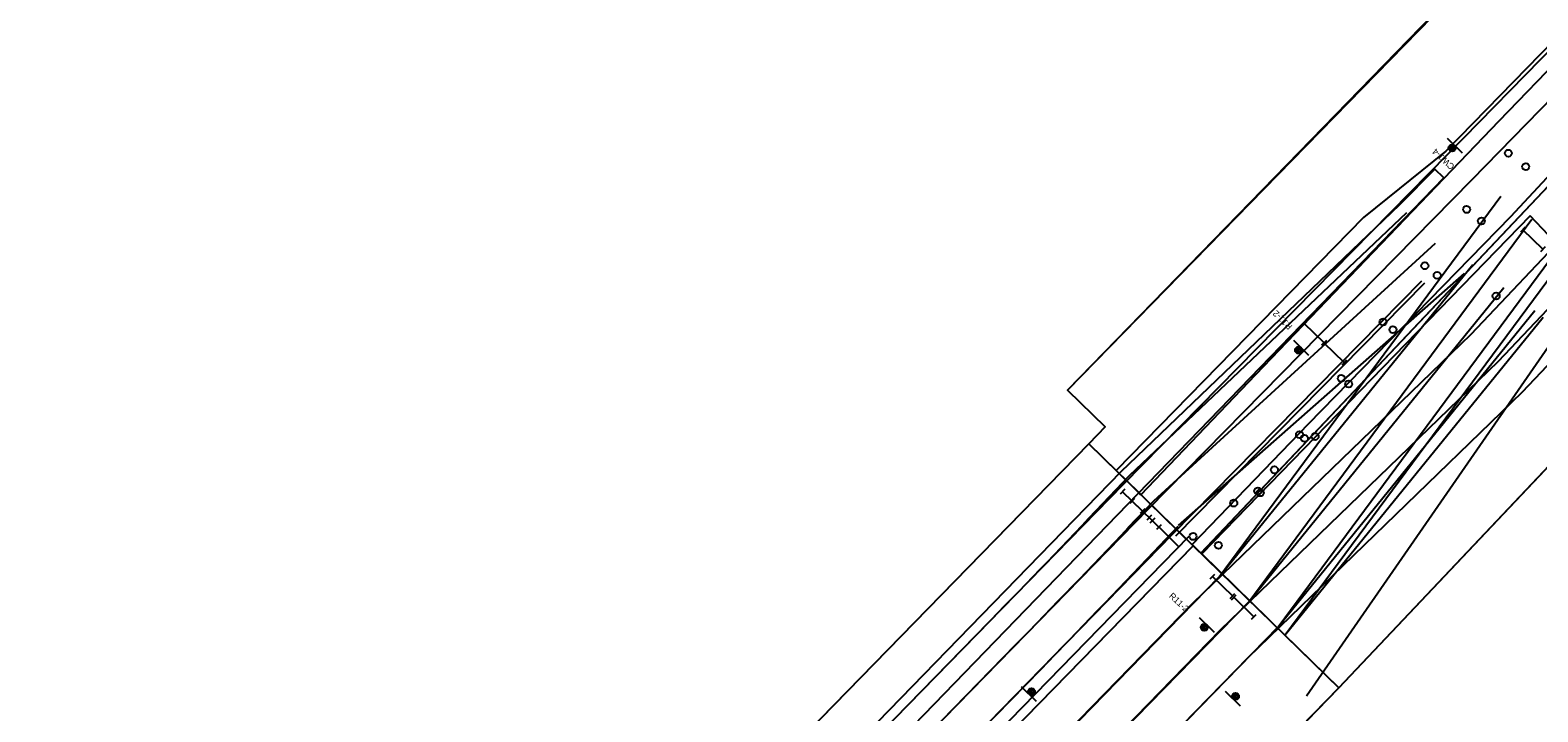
# Model space of a CAD drawing. Extents: x 2252379 to 2256472, y 13788212 to 13792539.
# Drawn here: x 2255390.1 to 2255820.2, y 13791557.4 to 13791752 of the extents above; entities that cross this region are included whole.
import ezdxf

# ---------------------------------------------------------------- set-up
doc = ezdxf.new("R2010")
doc.units = 0
for name, color, linetype in [('D_TCP_OVERALL_PATT', 7, 'Continuous'), ('D_TCP_PH_1_BARREL', 7, 'Continuous'), ('D_TCP_PH_1_BARRIER', 7, 'Continuous'), ('D_TCP_PH_1_MISC', 7, 'Continuous'), ('D_TCP_PH_1_PATT', 7, 'Continuous'), ('D_TCP_PH_1_SIGN', 7, 'Continuous'), ('D_TCP_PH_1_TEMP_PVMNT', 7, 'Continuous'), ('D_TCP_PH_1_WZPM_NRMV_4IN_W_SLD', 7, 'Continuous'), ('D_TCP_PH_1_WZPM_RMV_4IN_Y_SLD', 7, 'Continuous'), ('D_TCP_PH_1A_BARREL', 7, 'Continuous'), ('D_TCP_PH_1A_BARRIER', 7, 'Continuous'), ('D_TCP_PH_1A_PATT', 7, 'Continuous'), ('D_TCP_PH_1A_SIGN', 7, 'Continuous'), ('D_TCP_PH_1A_TEMP_DRN', 7, 'Continuous'), ('D_TCP_PH_1A_TEMP_PVMNT', 7, 'Continuous'), ('D_TCP_PH_1A_WZPM_NRMV_4IN_W_SLD', 7, 'Continuous'), ('D_TCP_PH_1A_WZPM_RMV_4IN_Y_SLD', 7, 'Continuous'), ('D_TCP_PH_1B_BARREL', 7, 'Continuous'), ('D_TCP_PH_1B_BARRIER', 7, 'Continuous'), ('D_TCP_PH_1B_TEMP_PVMNT', 7, 'Continuous'), ('D_TCP_PH_1B_WZPM_NRMV_4IN_W_SLD', 7, 'Continuous'), ('D_TCP_PH_1B_WZPM_RMV_4IN_Y_SLD', 7, 'Continuous'), ('D_TCP_PH_2_BARRIER', 7, 'Continuous'), ('D_TCP_PH_2_MISC', 7, 'Continuous'), ('D_TCP_PH_2_PATT', 7, 'Continuous'), ('D_TCP_PH_2_TEMP_PVMNT', 7, 'Continuous'), ('D_TCP_PH_2_WZPM_NRMV_4IN_W_SLD', 7, 'Continuous'), ('D_TCP_PH_2_WZPM_NRMV_4IN_Y_SLD', 7, 'Continuous'), ('D_TCP_PH_2A_BARREL', 7, 'Continuous'), ('D_TCP_PH_2A_PATT', 7, 'Continuous'), ('D_TCP_PH_2A_WZPM_NRMV_4IN_W_SLD', 7, 'Continuous'), ('D_TCP_PH_2A_WZPM_RMV_4IN_Y_SLD', 7, 'Continuous'), ('E_Structure_Sign_Sign And Post Single_SGN', 7, 'Continuous'), ('Level 1', 7, 'Continuous'), ('SIGN_DESCR', 7, 'Continuous')]:
    doc.layers.add(name, color=color, linetype=linetype)

# ---------------------------------------------------------------- blocks, each defined once
blk = doc.blocks.new('TYP3')
at = {"layer": 'Level 1'}
for p, q in [((-0.165, 0.04), (-0.165, -0.04)), ((0.163, 0), (-0.163, 0)), ((0.163, 0.04), (0.163, -0.04))]:
    blk.add_line(p, q, dxfattribs=at)
blk = doc.blocks.new('SGN')
at = {"layer": 'E_Structure_Sign_Sign And Post Single_SGN'}
blk.add_line((0.6, -0.2), (-0.6, -0.2), dxfattribs=at)
for radius in [0.2, 0.137, 0.0611]:
    blk.add_circle((0, 0), radius, dxfattribs=at)

msp = doc.modelspace()

# ---------------------------------------------------------------- linework, layer by layer
at = {"layer": 'D_TCP_OVERALL_PATT'}
for p, q in [((2255859.06, 13791745.48), (2255724.02, 13791602.73)), ((2255724.02, 13791602.73), (2255858.62, 13791745.02)), ((2255685.97, 13791649.23), (2255696.75, 13791638.72)), ((2255696.75, 13791638.72), (2255692.07, 13791633.92)), ((2255692.07, 13791633.92), (2255472.33, 13791408.61)), ((2255720.66, 13791606.02), (2255692.07, 13791633.92)), ((2255692.07, 13791633.92), (2255724.02, 13791602.73)), ((2255720.66, 13791606.02), (2255692.07, 13791633.92)), ((2255721.86, 13791604.85), (2255480.34, 13791357.3)), ((2255483.41, 13791360.45), (2255721.86, 13791604.85)), ((2255503.41, 13791380.95), (2255721.86, 13791604.85)), ((2255760.02, 13791567.61), (2255720.66, 13791606.02)), ((2255721.86, 13791604.85), (2255720.66, 13791606.02)), ((2255763.39, 13791564.32), (2255721.86, 13791604.85))]:
    msp.add_line(p, q, dxfattribs=at)
for points in [[(2256262.44, 13792241.68), (2255950.04, 13791921.35), (2255949.84, 13791921.15), (2255818.04, 13791784.57), (2255685.97, 13791649.23)], [(2255763.39, 13791564.32), (2255898.58, 13791707.23), (2255898.79, 13791707.44)], [(2255692.07, 13791633.92), (2255473.67, 13791409.98), (2255472.33, 13791408.61)], [(2255724.02, 13791602.73), (2255724.02, 13791602.73), (2255760.02, 13791567.61), (2255763.39, 13791564.32)], [(2255104.28, 13790888.18), (2255118.36, 13790881.14), (2255128.85, 13790888.25), (2255137.45, 13790895.94), (2255142.38, 13790905.75), (2255131.78, 13790916.36), (2255285.15, 13791073.53), (2255300.44, 13791089.2), (2255318.42, 13791107.62), (2255362.49, 13791152.79), (2255763.39, 13791564.32)]]:
    msp.add_lwpolyline(points, dxfattribs=at)
at = {"layer": 'D_TCP_PH_1_BARREL'}
for centre in [(2255756.65, 13791636), (2255745.04, 13791626.49), (2255733.44, 13791616.99), (2255721.83, 13791607.48)]:
    msp.add_circle(centre, 1, dxfattribs=at)
at = {"layer": 'D_TCP_PH_1_BARRIER'}
msp.add_line((2255497.24, 13791378.38), (2255720.62, 13791607.51), dxfattribs=at)
at = {"layer": 'D_TCP_PH_1_PATT'}
for p, q in [((2255721.86, 13791604.85), (2255480.34, 13791357.3)), ((2255763.39, 13791564.32), (2255721.86, 13791604.85))]:
    msp.add_line(p, q, dxfattribs=at)
msp.add_lwpolyline([(2255091.3, 13790894.58), (2255104.25, 13790888.15), (2255118.36, 13790881.14), (2255128.85, 13790888.25), (2255137.45, 13790895.94), (2255142.38, 13790905.75), (2255131.78, 13790916.36), (2255295.32, 13791083.95), (2255307.58, 13791096.52), (2255322.25, 13791111.55), (2255663.82, 13791461.58), (2255763.39, 13791564.32)], dxfattribs=at)
at = {"layer": 'D_TCP_PH_1_TEMP_PVMNT'}
for p, q in [((2255488.15, 13791394.52), (2255793.37, 13791709.82)), ((2255701.25, 13791625.9), (2255484.24, 13791402.88))]:
    msp.add_line(p, q, dxfattribs=at)
msp.add_lwpolyline([(2255793.37, 13791709.82), (2255790.81, 13791712.31), (2255780.7, 13791702.08), (2255701.25, 13791625.9)], dxfattribs=at)
at = {"layer": 'D_TCP_PH_1_WZPM_NRMV_4IN_W_SLD'}
for p, q in [((2255703.66, 13791624.86), (2255782.76, 13791699.91)), ((2255717.66, 13791610.56), (2255799.28, 13791682.49)), ((2255696.1, 13791616.87), (2255703.66, 13791624.86)), ((2255710.63, 13791603.12), (2255717.56, 13791610.45)), ((2255485.25, 13791400.28), (2255664.15, 13791583.61)), ((2255488.75, 13791375.24), (2255678.46, 13791569.64))]:
    msp.add_line(p, q, dxfattribs=at)
for radius in [2970, 2990]:
    msp.add_arc((2253538.53, 13793657.89), radius, 315.70035, 316.59007, dxfattribs=at)
at = {"layer": 'D_TCP_PH_1_WZPM_RMV_4IN_Y_SLD'}
for p, q in [((2255710.61, 13791617.66), (2255791.02, 13791691.2)), ((2255703.36, 13791610), (2255710.61, 13791617.66)), ((2255484.04, 13791384.73), (2255671.3, 13791576.63))]:
    msp.add_line(p, q, dxfattribs=at)
msp.add_arc((2253538.53, 13793657.89), 2980, 315.70035, 316.59007, dxfattribs=at)
at = {"layer": 'D_TCP_PH_1A_BARREL'}
for centre in [(2255816.71, 13791713.02), (2255804.08, 13791697.51), (2255791.46, 13791681.99), (2255778.84, 13791666.48), (2255766.22, 13791650.96), (2255753.6, 13791635.45), (2255740.98, 13791619.93), (2255729.05, 13791604.92)]:
    msp.add_circle(centre, 1, dxfattribs=at)
at = {"layer": 'D_TCP_PH_1A_BARRIER'}
for p, q in [((2255754.13, 13791669.01), (2255752.79, 13791667.63)), ((2255759.19, 13791662.73), (2255753.5, 13791668.28)), ((2255759.86, 13791663.42), (2255758.51, 13791662.04))]:
    msp.add_line(p, q, dxfattribs=at)
at = {"layer": 'D_TCP_PH_1A_PATT'}
for p, q in [((2255692.07, 13791633.92), (2255473.67, 13791409.98)), ((2255721.86, 13791604.85), (2255692.07, 13791633.92)), ((2255503.41, 13791380.95), (2255721.86, 13791604.85))]:
    msp.add_line(p, q, dxfattribs=at)
at = {"layer": 'D_TCP_PH_1A_TEMP_DRN'}
msp.add_line((2255828.27, 13791668.94), (2255754.22, 13791561.89), dxfattribs=at)
at = {"layer": 'D_TCP_PH_1A_TEMP_PVMNT'}
for p, q in [((2255748.05, 13791579.29), (2255821.67, 13791670.08)), ((2255721.54, 13791605.16), (2255748.05, 13791579.29)), ((2255721.54, 13791605.16), (2255748.05, 13791579.29))]:
    msp.add_line(p, q, dxfattribs=at)
for points in [[(2255837.05, 13791724.46), (2255824, 13791711.16), (2255812.42, 13791698.73)], [(2255837.05, 13791724.46), (2255824, 13791711.16), (2255812.42, 13791698.73)], [(2255812.42, 13791698.73), (2255754.67, 13791639.55), (2255721.54, 13791605.16)], [(2255812.42, 13791698.73), (2255754.67, 13791639.55), (2255721.54, 13791605.16)]]:
    msp.add_lwpolyline(points, dxfattribs=at)
at = {"layer": 'D_TCP_PH_1A_WZPM_NRMV_4IN_W_SLD'}
for p, q in [((2255729.3, 13791595.99), (2255801.64, 13791685.07)), ((2255746.09, 13791581.7), (2255819.34, 13791671.97)), ((2255511.26, 13791372.53), (2255729.3, 13791595.99)), ((2255516.79, 13791346.7), (2255746.09, 13791581.7))]:
    msp.add_line(p, q, dxfattribs=at)
at = {"layer": 'D_TCP_PH_1A_WZPM_RMV_4IN_Y_SLD'}
for p, q in [((2255737.7, 13791588.84), (2255810.49, 13791678.52)), ((2255508.92, 13791354.38), (2255737.7, 13791588.84))]:
    msp.add_line(p, q, dxfattribs=at)
at = {"layer": 'D_TCP_PH_1B_BARREL'}
for centre in [(2255811.76, 13791716.85), (2255799.85, 13791700.79), (2255787.94, 13791684.72), (2255776.02, 13791668.65), (2255764.11, 13791652.59), (2255752.2, 13791636.52), (2255740.29, 13791620.45), (2255729.05, 13791604.92)]:
    msp.add_circle(centre, 1, dxfattribs=at)
at = {"layer": 'D_TCP_PH_1B_TEMP_PVMNT'}
for p, q in [((2255817.95, 13791698.97), (2255724.29, 13791602.48)), ((2255828.49, 13791687.98), (2255817.95, 13791698.97)), ((2255748.05, 13791579.29), (2255828.49, 13791687.98)), ((2255724.29, 13791602.48), (2255748.05, 13791579.29))]:
    msp.add_line(p, q, dxfattribs=at)
at = {"layer": 'D_TCP_PH_1B_WZPM_NRMV_4IN_W_SLD'}
for p, q in [((2255729.3, 13791595.99), (2255809.65, 13791704.54)), ((2255746.09, 13791581.7), (2255827.33, 13791691.45)), ((2255501.04, 13791362.06), (2255729.3, 13791595.99)), ((2255516.79, 13791346.7), (2255746.09, 13791581.7))]:
    msp.add_line(p, q, dxfattribs=at)
at = {"layer": 'D_TCP_PH_1B_WZPM_RMV_4IN_Y_SLD'}
for p, q in [((2255737.7, 13791588.84), (2255818.49, 13791697.99)), ((2255508.92, 13791354.38), (2255737.7, 13791588.84))]:
    msp.add_line(p, q, dxfattribs=at)
at = {"layer": 'D_TCP_PH_2_BARRIER'}
msp.add_lwpolyline([(2255787.8, 13791679.72), (2255716.82, 13791607.52)], dxfattribs=at)
at = {"layer": 'D_TCP_PH_2_PATT'}
for points in [[(2255724.02, 13791602.73), (2255763.39, 13791564.32), (2255860.93, 13791667.42), (2255898.79, 13791707.44), (2255996.34, 13791810.56), (2256028.89, 13791844.66), (2256225.09, 13792045.83), (2256221.59, 13792049.77), (2256329.19, 13792160.1), (2256336.4, 13792159.97), (2256381.46, 13792159.13), (2256415.88, 13792189.35), (2256355.41, 13792258.24)], [(2255963.47, 13791855.85), (2255947.31, 13791838.77), (2255878.59, 13791766.12), (2255809.87, 13791693.48), (2255741.14, 13791620.83), (2255724.02, 13791602.73)]]:
    msp.add_lwpolyline(points, dxfattribs=at)
at = {"layer": 'D_TCP_PH_2_TEMP_PVMNT'}
for p, q in [((2255824.74, 13791748.96), (2255793.95, 13791717.4)), ((2255793.95, 13791717.4), (2255770.4, 13791698.52)), ((2255770.4, 13791698.52), (2255699.9, 13791626.27)), ((2255699.9, 13791626.27), (2255706.25, 13791620.07)), ((2255706.25, 13791620.07), (2255706.94, 13791619.4))]:
    msp.add_line(p, q, dxfattribs=at)
msp.add_lwpolyline([(2255706.94, 13791619.4), (2255739.78, 13791653.65), (2255809.14, 13791726.04), (2255828.07, 13791745.71)], dxfattribs=at)
at = {"layer": 'D_TCP_PH_2_WZPM_NRMV_4IN_W_SLD'}
for p, q in [((2255702, 13791622.4), (2255794.62, 13791716.66)), ((2255615.61, 13791533.87), (2255702, 13791622.4))]:
    msp.add_line(p, q, dxfattribs=at)
for points in [[(2255794.62, 13791716.66), (2255825.46, 13791748.26)], [(2255715.99, 13791608.1), (2255787.07, 13791680.43)], [(2255629.93, 13791519.9), (2255715.99, 13791608.1)]]:
    msp.add_lwpolyline(points, dxfattribs=at)
at = {"layer": 'D_TCP_PH_2_WZPM_NRMV_4IN_Y_SLD'}
for p, q in [((2255709.11, 13791615.37), (2255801.35, 13791709.24)), ((2255622.77, 13791526.88), (2255709.11, 13791615.37))]:
    msp.add_line(p, q, dxfattribs=at)
msp.add_lwpolyline([(2255801.35, 13791709.24), (2255832.61, 13791741.28)], dxfattribs=at)
at = {"layer": 'D_TCP_PH_2A_BARREL'}
msp.add_circle((2255808.28, 13791676.1), 1, dxfattribs=at)
at = {"layer": 'D_TCP_PH_2A_PATT'}
msp.add_line((2255724.02, 13791602.73), (2255741.14, 13791620.83), dxfattribs=at)
for points in [[(2256355.41, 13792258.24), (2256294.68, 13792327.44), (2256278.09, 13792313.37), (2256275.37, 13792310.98), (2256266.11, 13792319.83), (2256265.3, 13792302.52), (2256262.44, 13792241.68), (2255685.97, 13791649.23), (2255696.75, 13791638.72), (2255692.07, 13791633.92), (2255724.02, 13791602.73)], [(2255741.14, 13791620.83), (2255809.87, 13791693.48), (2255878.59, 13791766.12)]]:
    msp.add_lwpolyline(points, dxfattribs=at)
at = {"layer": 'D_TCP_PH_2A_WZPM_NRMV_4IN_W_SLD'}
for p, q in [((2255801.14, 13791665.2), (2255970.51, 13791844.64)), ((2255815.84, 13791648.73), (2255986.42, 13791829.45))]:
    msp.add_line(p, q, dxfattribs=at)
for points in [[(2255642.78, 13791507.31), (2255721.85, 13791588.58), (2255801.14, 13791665.2)], [(2255658.53, 13791491.94), (2255737.61, 13791573), (2255815.84, 13791648.73)]]:
    msp.add_lwpolyline(points, dxfattribs=at)
at = {"layer": 'D_TCP_PH_2A_WZPM_RMV_4IN_Y_SLD'}
msp.add_line((2255808.97, 13791657.47), (2255978.47, 13791837.05), dxfattribs=at)
msp.add_lwpolyline([(2255650.65, 13791499.63), (2255729.67, 13791580.85), (2255808.97, 13791657.47)], dxfattribs=at)

# ---------------------------------------------------------------- block references
at = {"layer": 'D_TCP_PH_1_MISC', "xscale": 24.38416784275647, "yscale": 24.38416784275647, "rotation": 135.7030812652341}
for p in [(2255730.19, 13791593.29), (2255736.27, 13791587.36)]:
    msp.add_blockref('TYP3', p, dxfattribs=at)
at = {"layer": 'D_TCP_PH_1_SIGN', "xscale": 4.999999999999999}
for p, yscale, rotation in [((2255795.73, 13791718.34), 4.999999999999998, 135.70308123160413), ((2255725.04, 13791581.54), 4.999999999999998, 135.70308123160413), ((2255675.74, 13791563.15), 4.9999999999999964, -44.445000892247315)]:
    msp.add_blockref('SGN', p, dxfattribs=dict(at, yscale=yscale, rotation=rotation))
at = {"layer": 'D_TCP_PH_1A_BARRIER', "xscale": 24.384167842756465, "yscale": 24.384167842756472, "rotation": -44.280443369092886}
for p in [(2255762.06, 13791659.85), (2255704.58, 13791617.46), (2255704.58, 13791617.46), (2255712.21, 13791610.02), (2255712.21, 13791610.02)]:
    msp.add_blockref('TYP3', p, dxfattribs=at)
at = {"layer": 'D_TCP_PH_1A_SIGN'}
for p, xscale, yscale, rotation in [((2255751.92, 13791660.64), 5, 5.000000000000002, 135.4039053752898), ((2255733.93, 13791561.84), 5.000000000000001, 5.000000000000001, -44.59609462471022)]:
    msp.add_blockref('SGN', p, dxfattribs=dict(at, xscale=xscale, yscale=yscale, rotation=rotation))
at = {"layer": 'D_TCP_PH_1B_BARRIER', "xscale": 24.384167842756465, "yscale": 24.384167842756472, "rotation": -44.280443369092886}
for p in [(2255707.35, 13791614.76), (2255714.97, 13791607.32)]:
    msp.add_blockref('TYP3', p, dxfattribs=at)
at = {"layer": 'D_TCP_PH_2_MISC', "xscale": 24.384167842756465, "yscale": 24.384167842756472, "rotation": -44.28207184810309}
msp.add_blockref('TYP3', (2255818.76, 13791692.21), dxfattribs=at)

# ---------------------------------------------------------------- texts
at = {"layer": 'SIGN_DESCR'}
for s, rotation, p in [('CW1-4', 136.9063, (2255796.56, 13791713.24)), ('R11-2', 135.4039, (2255750.31, 13791667.56)), ('R11-2', 317.0544, (2255714.8, 13791590.28))]:
    msp.add_text(s, height=1.8, rotation=rotation, dxfattribs=at).set_placement(p)

doc.saveas('drawing.dxf')
